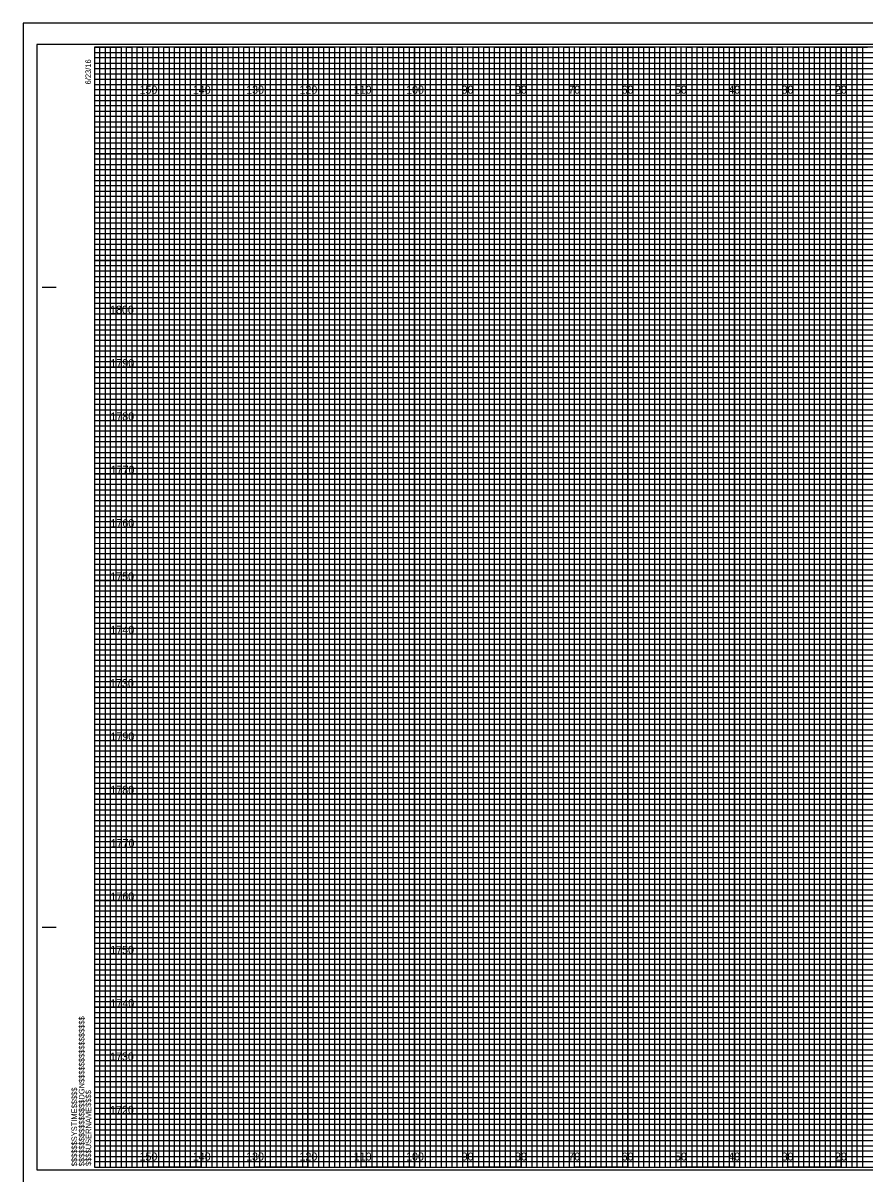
# Model space of a CAD drawing. Extents: x -419 to 4739, y -630 to 13534.
# Drawn here: x 476.2 to 634.1, y 211.3 to 427 of the extents above; entities that cross this region are included whole.
import ezdxf

# ---------------------------------------------------------------- set-up
doc = ezdxf.new("R2010")
doc.units = 0
for name, color, linetype in [('Old_Level_62', 7, 'Continuous'), ('Pattern 1', 7, 'Continuous'), ('Pattern 18', 7, 'Continuous'), ('Pattern 4', 7, 'Continuous'), ('Pattern 5', 7, 'Continuous'), ('Prop Dimension', 7, 'Continuous'), ('Prop Horizontal Alignment', 7, 'Continuous'), ('Raster_Level_0', 7, 'Continuous'), ('Scratch_Level_0', 7, 'Continuous'), ('Scratch_Level_3', 7, 'Continuous'), ('Scratch_Level_5', 7, 'Continuous')]:
    doc.layers.add(name, color=color, linetype=linetype)

msp = doc.modelspace()

# ---------------------------------------------------------------- linework, layer by layer
at = {"layer": 'Old_Level_62'}
for p, q in [((479.78, 377.54), (482.28, 377.54)), ((479.88, 377.54), (482.38, 377.54)), ((479.78, 257.54), (482.28, 257.54)), ((479.88, 257.54), (482.38, 257.54)), ((489.58, 212.54), (489.58, 212.54)), ((489.58, 212.54), (489.58, 212.54)), ((489.58, 212.54), (489.58, 212.54)), ((489.58, 212.54), (489.58, 212.54)), ((489.58, 212.54), (489.58, 212.54)), ((489.58, 212.54), (489.58, 212.54)), ((489.58, 212.54), (489.58, 212.54))]:
    msp.add_line(p, q, dxfattribs=at)
msp.add_lwpolyline([(809.58, 422.54), (489.58, 422.54), (489.58, 212.54), (809.58, 212.54)], close=True, dxfattribs=at)
at = {"layer": 'Pattern 18'}
msp.add_lwpolyline([(476.18, 208.04), (812.88, 208.04), (812.88, 427.04), (476.18, 427.04)], close=True, dxfattribs=at)
at = {"layer": 'Pattern 4'}
for p, q in [((489.58, 421.54), (749.58, 421.54)), ((749.58, 420.52), (489.58, 420.52)), ((489.58, 420.52), (489.58, 419.54)), ((489.58, 419.54), (749.58, 419.54)), ((749.58, 418.43), (489.58, 418.43)), ((489.58, 418.43), (489.58, 416.54)), ((489.58, 416.54), (809.58, 416.54))]:
    msp.add_line(p, q, dxfattribs=at)
for points in [[(489.58, 415.54), (759.58, 415.54), (809.58, 415.54), (809.58, 414.54), (489.58, 414.54)], [(489.58, 413.54), (809.58, 413.54), (809.58, 411.54), (489.58, 411.54)], [(489.58, 410.54), (809.58, 410.54), (809.58, 409.54), (489.58, 409.52)], [(489.58, 408.54), (809.58, 408.54), (809.58, 406.54), (489.58, 406.54)], [(489.58, 405.54), (809.58, 405.54), (809.58, 404.54), (489.58, 404.54)], [(489.58, 403.54), (809.58, 403.54), (809.58, 401.54), (489.58, 401.54)], [(489.58, 400.54), (809.58, 400.54), (809.58, 399.54), (489.58, 399.54)], [(489.58, 398.54), (809.58, 398.54), (809.58, 396.54), (489.58, 396.54)], [(489.58, 395.54), (809.58, 395.54), (809.58, 394.54), (489.58, 394.54)], [(489.58, 393.54), (809.58, 393.54), (809.58, 391.54), (489.58, 391.54)], [(489.58, 390.54), (809.58, 390.54), (809.58, 389.54), (489.58, 389.54)], [(489.58, 388.54), (809.58, 388.54), (809.58, 386.49), (809.58, 385.54), (809.58, 384.54), (489.58, 384.54)], [(489.58, 386.54), (809.58, 386.54), (809.58, 385.54), (489.58, 385.54)], [(489.58, 383.54), (809.58, 383.54), (809.58, 381.54), (489.58, 381.57)], [(489.58, 381.57), (809.58, 381.54), (809.58, 380.54), (489.58, 380.54)], [(489.58, 379.54), (809.58, 379.54), (809.58, 378.54), (489.58, 378.54)], [(489.58, 376.54), (809.58, 376.54), (809.58, 375.54), (489.58, 375.54)], [(489.58, 374.54), (809.58, 374.54), (809.58, 373.54), (489.58, 373.54)], [(489.51, 371.43), (809.58, 371.43), (809.58, 370.42), (489.51, 370.42)], [(489.58, 369.54), (809.58, 369.54), (809.58, 368.54), (489.58, 368.54)], [(489.58, 366.54), (809.58, 366.54), (809.58, 365.54), (489.58, 365.54)], [(489.58, 364.54), (809.58, 364.54), (809.58, 363.54), (489.58, 363.54)], [(489.58, 361.54), (809.58, 361.54), (809.58, 360.54), (489.58, 360.54)], [(489.58, 359.54), (809.58, 359.54), (809.58, 358.54), (489.58, 358.54)], [(489.58, 356.54), (809.58, 356.54), (809.58, 355.54), (489.58, 355.54)], [(489.58, 354.54), (809.58, 354.54), (809.58, 353.54), (489.58, 353.54)], [(489.58, 351.54), (809.58, 351.54), (809.57, 350.52), (489.58, 350.54)], [(489.58, 349.54), (809.58, 349.54), (809.58, 348.54), (489.58, 348.54)], [(489.58, 346.54), (809.58, 346.54), (809.58, 345.54), (489.58, 345.54)], [(489.58, 344.54), (809.58, 344.54), (809.58, 343.54), (489.58, 343.54)], [(489.58, 341.54), (809.58, 341.54), (809.58, 340.54), (489.58, 340.54)], [(489.58, 339.54), (809.58, 339.54), (809.58, 338.54), (489.58, 338.54)], [(489.58, 336.54), (809.58, 336.54), (809.58, 335.54), (489.58, 335.54)], [(489.58, 334.54), (809.58, 334.54), (809.58, 333.54), (489.58, 333.54)], [(489.58, 331.54), (809.58, 331.54), (809.58, 330.54), (489.58, 330.54)], [(489.58, 329.53), (809.65, 329.45), (809.58, 328.54), (489.58, 328.54)], [(489.58, 326.54), (809.58, 326.54), (809.58, 325.54), (489.58, 325.54)], [(489.58, 324.54), (809.58, 324.54), (809.58, 323.54), (489.58, 323.54)], [(489.58, 321.54), (809.58, 321.54), (809.58, 320.54), (489.58, 320.54)], [(489.58, 319.54), (809.58, 319.54), (809.58, 318.54), (489.58, 318.54)], [(489.58, 316.54), (809.58, 316.54), (809.58, 315.54), (489.58, 315.54)], [(489.58, 314.54), (809.58, 314.54), (809.58, 313.54), (489.58, 313.54)], [(489.58, 311.54), (809.58, 311.54), (809.58, 310.54), (489.58, 310.54)], [(489.58, 309.54), (809.58, 309.54), (809.58, 308.54), (489.58, 308.54)], [(489.58, 306.54), (809.58, 306.54), (809.58, 305.54), (489.58, 305.54)], [(489.58, 304.54), (809.58, 304.54), (809.58, 303.54), (489.58, 303.54)], [(489.58, 301.54), (809.58, 301.54), (809.58, 300.54), (489.58, 300.54)], [(489.58, 299.54), (809.58, 299.54), (809.58, 298.54), (489.58, 298.54)], [(489.58, 296.54), (809.58, 296.54), (809.58, 295.54), (489.58, 295.54)], [(489.58, 294.54), (809.58, 294.54), (809.58, 293.54), (489.58, 293.54)], [(489.58, 291.54), (809.58, 291.54), (809.57, 290.52), (489.58, 290.54)], [(489.58, 289.54), (809.58, 289.54), (809.58, 288.54), (489.58, 288.54)], [(489.58, 286.54), (809.58, 286.54), (809.58, 285.54), (489.58, 285.54)], [(489.58, 284.54), (809.58, 284.54), (809.58, 283.54), (489.58, 283.54)], [(489.58, 281.54), (809.58, 281.54), (809.58, 280.54), (489.58, 280.54)], [(489.58, 279.54), (809.58, 279.54), (809.58, 278.54), (489.58, 278.54)], [(489.58, 276.54), (809.58, 276.54), (809.58, 275.54), (489.58, 275.54)], [(489.58, 274.54), (809.58, 274.54), (809.58, 273.54), (489.58, 273.54)], [(489.58, 271.54), (809.58, 271.54), (809.58, 270.54), (489.58, 270.54)], [(489.58, 269.53), (809.65, 269.45), (809.58, 268.54), (489.58, 268.54)], [(489.58, 266.54), (809.58, 266.54), (809.58, 265.54), (489.58, 265.54)], [(489.58, 264.54), (809.58, 264.54), (809.58, 263.54), (489.58, 263.54)], [(489.58, 261.54), (809.58, 261.54), (809.58, 260.54), (489.58, 260.54)], [(489.58, 259.54), (809.58, 259.54), (809.58, 258.54), (489.58, 258.54)], [(489.58, 256.54), (809.58, 256.54), (809.58, 255.54), (489.58, 255.54)], [(489.58, 254.54), (809.58, 254.54), (809.58, 253.54), (489.58, 253.54)], [(489.58, 251.54), (809.58, 251.54), (809.58, 250.54), (489.58, 250.54)], [(489.58, 249.54), (809.58, 249.54), (809.58, 248.54), (489.58, 248.54)], [(489.58, 246.54), (809.58, 246.54), (809.58, 245.54), (489.58, 245.54)], [(489.58, 244.54), (809.58, 244.54), (809.58, 243.54), (489.58, 243.54)], [(489.58, 241.54), (809.58, 241.54), (809.58, 240.54), (489.58, 240.54)], [(489.58, 239.54), (809.58, 239.54), (809.58, 238.54), (489.58, 238.54)], [(489.58, 236.54), (809.58, 236.54), (809.58, 235.54), (489.58, 235.54)], [(489.58, 234.54), (809.58, 234.54), (809.58, 233.54), (489.58, 233.54)], [(489.58, 231.54), (809.58, 231.54), (809.58, 230.54), (489.58, 230.54)], [(489.58, 229.54), (809.58, 229.54), (809.58, 228.54), (489.58, 228.54)], [(489.58, 226.54), (809.58, 226.54), (809.58, 225.54), (489.58, 225.54)], [(489.58, 224.54), (809.58, 224.54), (809.58, 223.54), (489.58, 223.54)], [(489.58, 221.54), (809.58, 221.54), (809.58, 220.54), (489.58, 220.54)], [(489.58, 219.54), (809.58, 219.54), (809.58, 218.54), (489.58, 218.54)], [(489.58, 216.54), (809.58, 216.54), (809.58, 215.54), (489.58, 215.54)], [(489.58, 214.54), (809.58, 214.54), (809.58, 213.54), (489.58, 213.54)]]:
    msp.add_lwpolyline(points, dxfattribs=at)
at = {"layer": 'Pattern 5'}
for p, q in [((812.88, 427.04), (476.18, 427.04)), ((476.18, 427.04), (476.18, 208.04))]:
    msp.add_line(p, q, dxfattribs=at)
at = {"layer": 'Prop Dimension'}
for points in [[(489.58, 212.54), (490.58, 212.54), (490.58, 422.54), (491.58, 422.54), (491.58, 212.54)], [(491.58, 212.54), (492.58, 212.54), (492.58, 422.54), (493.58, 422.54), (493.58, 212.54)], [(494.58, 212.54), (495.58, 212.54), (495.58, 422.54), (496.58, 422.54), (496.58, 212.54)], [(496.58, 212.54), (497.58, 212.54), (497.58, 422.54), (498.58, 422.54), (498.58, 212.54)], [(499.58, 212.54), (500.58, 212.54), (500.58, 422.54), (501.58, 422.54), (501.58, 212.54)], [(501.58, 212.54), (502.58, 212.54), (502.58, 422.54), (503.58, 422.54), (503.58, 212.54)], [(504.58, 212.54), (505.58, 212.54), (505.58, 422.54), (506.58, 422.54), (506.58, 212.54)], [(506.58, 212.54), (507.58, 212.54), (507.58, 422.54), (508.58, 422.54), (508.58, 212.54)], [(509.58, 212.54), (510.58, 212.54), (510.58, 422.54), (511.58, 422.54), (511.58, 212.54)], [(511.58, 212.54), (512.58, 212.54), (512.58, 422.54), (513.58, 422.54), (513.58, 212.54)], [(514.58, 212.54), (515.58, 212.54), (515.58, 422.54), (516.58, 422.54), (516.58, 212.54)], [(516.58, 212.54), (517.58, 212.54), (517.58, 422.54), (518.58, 422.54), (518.58, 212.54)], [(519.58, 212.54), (520.58, 212.54), (520.58, 422.54), (521.58, 422.54), (521.58, 212.54)], [(521.58, 212.54), (522.58, 212.54), (522.58, 422.54), (523.58, 422.54), (523.58, 212.54)], [(524.58, 212.54), (525.58, 212.54), (525.58, 422.54), (526.58, 422.54), (526.58, 212.54)], [(526.58, 212.54), (527.58, 212.54), (527.58, 422.54), (528.58, 422.54), (528.58, 212.54)], [(529.58, 212.54), (530.58, 212.54), (530.58, 422.54), (531.58, 422.54), (531.58, 212.54)], [(531.58, 212.54), (532.58, 212.54), (532.58, 422.54), (533.58, 422.54), (533.58, 212.54)], [(534.58, 212.54), (535.58, 212.54), (535.58, 422.54), (536.58, 422.54), (536.58, 212.54)], [(536.58, 212.54), (537.58, 212.54), (537.58, 422.54), (538.58, 422.54), (538.58, 212.54)], [(539.58, 212.54), (540.58, 212.54), (540.58, 422.54), (541.58, 422.54), (541.58, 212.54)], [(541.58, 212.54), (542.58, 212.54), (542.58, 422.54), (543.58, 422.54), (543.58, 212.54)], [(544.58, 212.54), (545.58, 212.54), (545.58, 422.54), (546.58, 422.54), (546.58, 212.54)], [(546.58, 212.54), (547.58, 212.54), (547.58, 422.54), (548.58, 422.54), (548.58, 212.54)], [(549.58, 212.54), (550.58, 212.54), (550.58, 422.54), (551.58, 422.54), (551.58, 212.54)], [(551.58, 212.54), (552.58, 212.54), (552.58, 422.54), (553.58, 422.54), (553.58, 212.54)], [(554.58, 212.54), (555.58, 212.54), (555.58, 422.54), (556.58, 422.54), (556.58, 212.54)], [(556.58, 212.54), (557.58, 212.54), (557.58, 422.54), (558.58, 422.54), (558.58, 212.54)], [(559.58, 212.54), (560.58, 212.54), (560.58, 422.54), (561.58, 422.54), (561.58, 212.54)], [(561.58, 212.54), (562.58, 212.54), (562.58, 422.54), (563.58, 422.54), (563.58, 212.54)], [(564.58, 212.54), (565.58, 212.54), (565.58, 422.54), (566.58, 422.54), (566.58, 212.54)], [(566.58, 212.54), (567.58, 212.54), (567.58, 422.54), (568.58, 422.54), (568.58, 212.54)], [(569.58, 212.54), (570.58, 212.54), (570.58, 422.54), (571.58, 422.54), (571.58, 212.54)], [(571.58, 212.54), (572.58, 212.54), (572.58, 422.54), (573.58, 422.54), (573.58, 212.54)], [(574.58, 212.54), (575.58, 212.54), (575.58, 422.54), (576.58, 422.54), (576.58, 212.54)], [(576.58, 212.54), (577.58, 212.54), (577.58, 422.54), (578.58, 422.54), (578.58, 212.54)], [(579.58, 212.54), (580.58, 212.54), (580.58, 422.54), (581.58, 422.54), (581.58, 212.54)], [(581.58, 212.54), (582.58, 212.54), (582.58, 422.54), (583.58, 422.54), (583.58, 212.54)], [(584.58, 212.54), (585.58, 212.54), (585.58, 422.54), (586.58, 422.54), (586.58, 212.54)], [(586.58, 212.54), (587.58, 212.54), (587.58, 422.54), (588.58, 422.54), (588.58, 212.54)], [(589.58, 212.54), (590.58, 212.54), (590.58, 422.54), (591.58, 422.54), (591.58, 212.54)], [(591.58, 212.54), (592.58, 212.54), (592.58, 422.54), (593.58, 422.54), (593.58, 212.54)], [(594.58, 212.54), (595.58, 212.54), (595.58, 422.54), (596.58, 422.54), (596.58, 212.54)], [(596.58, 212.54), (597.58, 212.54), (597.58, 422.54), (598.58, 422.54), (598.58, 212.54)], [(599.58, 212.54), (600.58, 212.54), (600.58, 422.54), (601.58, 422.54), (601.58, 212.54)], [(601.58, 212.54), (602.58, 212.54), (602.58, 422.54), (603.58, 422.54), (603.58, 212.54)], [(604.58, 212.54), (605.58, 212.54), (605.58, 422.54), (606.58, 422.54), (606.58, 212.54)], [(606.58, 212.54), (607.58, 212.54), (607.58, 422.54), (608.58, 422.54), (608.58, 212.54)], [(609.58, 212.54), (610.58, 212.54), (610.58, 422.54), (611.58, 422.54), (611.58, 212.54)], [(611.58, 212.54), (612.58, 212.54), (612.58, 422.54), (613.58, 422.54), (613.58, 212.54)], [(614.58, 212.54), (615.58, 212.54), (615.58, 422.54), (616.58, 422.54), (616.58, 212.54)], [(616.58, 212.54), (617.58, 212.54), (617.58, 422.54), (618.58, 422.54), (618.58, 212.54)], [(619.58, 212.54), (620.58, 212.54), (620.58, 422.54), (621.58, 422.54), (621.58, 212.54)], [(621.58, 212.54), (622.58, 212.54), (622.58, 422.54), (623.58, 422.54), (623.58, 212.54)], [(624.58, 212.54), (625.58, 212.54), (625.58, 422.54), (626.58, 422.54), (626.58, 212.54)], [(626.58, 212.54), (627.58, 212.54), (627.58, 422.54), (628.58, 422.54), (628.58, 212.54)], [(629.58, 212.54), (630.58, 212.54), (630.58, 422.54), (631.58, 422.54), (631.58, 212.54)], [(631.58, 212.54), (632.58, 212.54), (632.58, 422.54), (633.58, 422.54), (633.58, 212.54)]]:
    msp.add_lwpolyline(points, dxfattribs=at)
at = {"layer": 'Prop Horizontal Alignment'}
for points in [[(489.58, 422.54), (494.58, 422.54), (494.58, 212.54), (504.58, 212.54), (504.58, 422.54), (514.58, 422.54), (514.58, 212.54), (524.58, 212.54), (524.58, 422.54), (534.58, 422.54), (534.58, 212.54), (544.58, 212.54), (544.58, 422.54), (554.58, 422.54), (554.58, 212.54), (564.58, 212.54), (564.58, 422.54), (574.58, 422.54), (574.58, 212.54), (584.58, 212.54), (584.58, 422.54), (594.58, 422.54), (594.58, 212.54), (604.58, 212.54), (604.58, 422.54), (614.58, 422.54), (614.58, 212.54), (624.58, 212.54), (624.58, 422.54), (634.58, 422.54)], [(489.58, 417.54), (764.58, 417.54)], [(489.58, 397.54), (809.58, 397.54), (809.58, 407.54), (489.58, 407.54)], [(489.58, 377.54), (809.58, 377.54), (809.58, 387.54), (489.58, 387.54)], [(489.58, 357.54), (809.58, 357.54), (809.58, 367.54), (489.58, 367.54)], [(489.58, 337.54), (809.58, 337.54), (809.58, 347.54), (489.58, 347.54)], [(489.58, 317.54), (809.58, 317.54), (809.58, 327.54), (489.58, 327.54)], [(489.58, 297.54), (809.58, 297.54), (809.58, 307.54), (489.58, 307.54)], [(489.58, 277.54), (809.58, 277.54), (809.58, 287.54), (489.58, 287.54)], [(489.58, 257.54), (809.58, 257.54), (809.58, 267.54), (489.58, 267.54)], [(489.58, 237.54), (809.58, 237.54), (809.58, 247.54), (489.58, 247.54)], [(489.58, 217.54), (809.58, 217.54), (809.58, 227.54), (489.58, 227.54)]]:
    msp.add_lwpolyline(points, dxfattribs=at)
at = {"layer": 'Scratch_Level_0'}
for p, q in [((499.58, 212.54), (499.58, 422.54)), ((509.58, 212.54), (509.58, 422.54)), ((519.58, 212.54), (519.58, 422.54)), ((529.58, 212.54), (529.58, 422.54)), ((539.58, 212.54), (539.58, 422.54)), ((549.58, 212.54), (549.58, 422.54)), ((559.58, 212.54), (559.58, 422.54)), ((569.58, 212.54), (569.58, 422.54)), ((579.58, 212.54), (579.58, 422.54)), ((589.58, 212.54), (589.58, 422.54)), ((599.58, 212.54), (599.58, 422.54)), ((609.58, 212.54), (609.58, 422.54)), ((619.58, 212.54), (619.58, 422.54)), ((629.58, 212.54), (629.58, 422.54)), ((489.58, 412.54), (809.58, 412.54)), ((489.58, 402.54), (809.58, 402.54)), ((489.58, 392.54), (809.58, 392.54)), ((489.58, 382.54), (809.58, 382.54)), ((489.58, 372.54), (809.58, 372.54)), ((489.58, 362.54), (809.58, 362.54)), ((489.58, 352.54), (809.58, 352.54)), ((489.58, 342.54), (809.58, 342.54)), ((489.58, 332.54), (809.58, 332.54)), ((489.58, 322.54), (809.58, 322.54)), ((489.58, 312.54), (809.58, 312.54)), ((489.58, 302.54), (809.58, 302.54)), ((489.58, 292.54), (809.58, 292.54)), ((489.58, 282.54), (809.58, 282.54)), ((489.58, 272.54), (809.58, 272.54)), ((489.58, 262.54), (809.58, 262.54)), ((489.58, 252.54), (809.58, 252.54)), ((489.58, 242.54), (809.58, 242.54)), ((489.58, 232.54), (809.58, 232.54)), ((489.58, 222.54), (809.58, 222.54))]:
    msp.add_line(p, q, dxfattribs=at)
at = {"layer": 'Scratch_Level_3'}
for p, q in [((499.58, 422.54), (489.58, 422.54)), ((499.58, 212.54), (499.58, 422.54)), ((519.58, 422.54), (509.58, 422.54)), ((509.58, 422.54), (509.58, 212.54)), ((519.58, 212.54), (519.58, 422.54)), ((539.58, 422.54), (529.58, 422.54)), ((529.58, 422.54), (529.58, 212.54)), ((539.58, 212.54), (539.58, 422.54)), ((559.58, 422.54), (549.58, 422.54)), ((549.58, 422.54), (549.58, 212.54)), ((559.58, 212.54), (559.58, 422.54)), ((579.58, 422.54), (569.58, 422.54)), ((569.58, 422.54), (569.58, 212.54)), ((579.58, 212.54), (579.58, 422.54)), ((599.58, 422.54), (589.58, 422.54)), ((589.58, 422.54), (589.58, 212.54)), ((599.58, 212.54), (599.58, 422.54)), ((619.58, 422.54), (609.58, 422.54)), ((609.58, 422.54), (609.58, 212.54)), ((619.58, 212.54), (619.58, 422.54)), ((639.58, 422.54), (629.58, 422.54)), ((629.58, 422.54), (629.58, 212.54)), ((509.58, 212.54), (499.58, 212.54)), ((529.58, 212.54), (519.58, 212.54)), ((549.58, 212.54), (539.58, 212.54)), ((569.58, 212.54), (559.58, 212.54)), ((589.58, 212.54), (579.58, 212.54)), ((609.58, 212.54), (599.58, 212.54)), ((629.58, 212.54), (619.58, 212.54))]:
    msp.add_line(p, q, dxfattribs=at)
for points in [[(489.58, 412.54), (809.58, 412.54), (809.58, 402.54), (489.58, 402.54)], [(489.58, 392.54), (809.58, 392.54), (809.58, 382.54), (489.58, 382.54)], [(489.58, 372.54), (809.58, 372.54), (809.58, 362.54), (489.58, 362.54)], [(489.58, 352.54), (809.58, 352.54), (809.58, 342.54), (489.58, 342.54)], [(489.58, 332.54), (809.58, 332.54), (809.58, 322.54), (489.58, 322.54)], [(489.58, 312.54), (809.58, 312.54), (809.58, 302.54), (489.58, 302.54)], [(489.58, 292.54), (809.58, 292.54), (809.58, 282.54), (489.58, 282.54)], [(489.58, 272.54), (809.58, 272.54), (809.58, 262.54), (489.58, 262.54)], [(489.58, 252.54), (809.58, 252.54), (809.58, 242.54), (489.58, 242.54)], [(489.58, 232.54), (809.58, 232.54), (809.58, 222.54), (489.58, 222.54)]]:
    msp.add_lwpolyline(points, dxfattribs=at)
at = {"layer": 'Scratch_Level_5'}
msp.add_lwpolyline([(478.78, 212.04), (811.98, 212.04), (811.98, 423.04), (478.78, 423.04)], close=True, dxfattribs=at)

# ---------------------------------------------------------------- texts
at = {"layer": 'Old_Level_62'}
for s, p in [('6/23/16', (488.93, 415.54)), ('$$$$$$$$$$$$$$$$DGN$$$$$$$$$$$$$$$$', (487.7, 212.72)), ('$$$$$$SYSTIME$$$$$', (486.32, 212.72)), ('$$$$USERNAME$$$$', (488.96, 212.77))]:
    msp.add_text(s, height=1.05, rotation=90, dxfattribs=at).set_placement(p)
at = {"layer": 'Pattern 1'}
for s, p in [('1800', (492.5, 372.54)), ('1790', (492.58, 362.54)), ('1780', (492.56, 352.54)), ('1770', (492.62, 342.54)), ('1760', (492.58, 332.54)), ('1750', (492.53, 322.54)), ('1740', (492.58, 312.54)), ('1730', (492.5, 302.54)), ('1790', (492.58, 292.54)), ('1780', (492.56, 282.54)), ('1770', (492.62, 272.54)), ('1760', (492.58, 262.54)), ('1750', (492.53, 252.54)), ('1740', (492.58, 242.54)), ('1730', (492.5, 232.54)), ('1720', (492.51, 222.54))]:
    msp.add_text(s, height=1.5, dxfattribs=at).set_placement(p)
at = {"layer": 'Raster_Level_0'}
for s, p in [('150', (498.02, 413.79)), ('140', (508.02, 413.79)), ('130', (518.02, 413.79)), ('120', (528.02, 413.79)), ('110', (538.2, 413.79)), ('100', (548.02, 413.79)), ('90', (558.44, 413.79)), ('80', (568.44, 413.79)), ('70', (578.44, 413.79)), ('60', (588.44, 413.79)), ('50', (598.44, 413.79)), ('40', (608.44, 413.79)), ('30', (618.44, 413.79)), ('20', (628.44, 413.79)), ('150', (498.02, 213.79)), ('140', (508.02, 213.79)), ('130', (518.02, 213.79)), ('120', (528.02, 213.79)), ('110', (538.2, 213.79)), ('100', (548.02, 213.79)), ('90', (558.44, 213.79)), ('80', (568.44, 213.79)), ('70', (578.44, 213.79)), ('60', (588.44, 213.79)), ('50', (598.44, 213.79)), ('40', (608.44, 213.79)), ('30', (618.44, 213.79)), ('20', (628.44, 213.79))]:
    msp.add_text(s, height=1.5, dxfattribs=at).set_placement(p)

doc.saveas('drawing.dxf')
